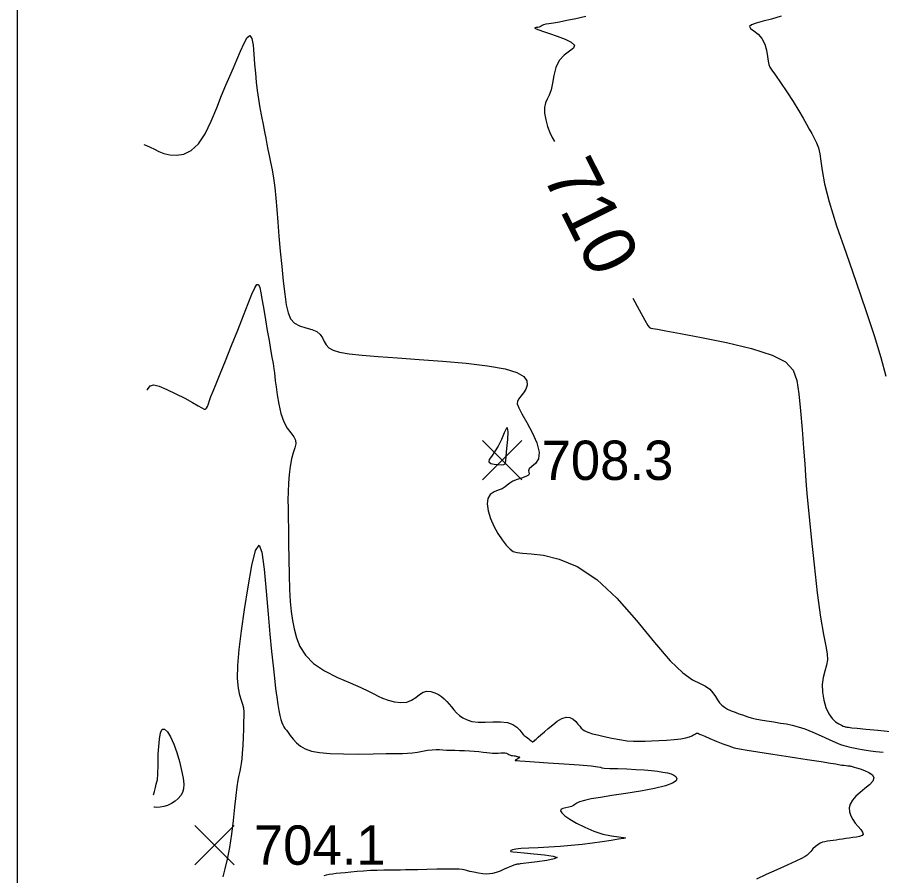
# Model space of a CAD drawing. Extents: x 2566142 to 2571431, y 418755 to 421584.
# Drawn here: x 2566164.4 to 2566493.5, y 419088.7 to 419415.7 of the extents above; entities that cross this region are included whole.
import ezdxf

# ---------------------------------------------------------------- set-up
doc = ezdxf.new("R2010")
doc.units = 0
for name, color, linetype in [('Contour_ADS_Label_Major', 7, 'Continuous'), ('Contour_ADS_Major', 7, 'Continuous'), ('Contour_ADS_Minor', 7, 'Continuous'), ('Contour_ADS_Spot_Elevation', 7, 'Continuous'), ('Contour_ADS_State_Plane_Border', 7, 'Continuous')]:
    doc.layers.add(name, color=color, linetype=linetype)

# ---------------------------------------------------------------- blocks, each defined once
blk = doc.blocks.new('S750')
at = {"layer": 'Contour_ADS_Spot_Elevation'}
for p, q in [((-0.5, 0.498), (0.5, -0.498)), ((-0.498, -0.5), (0.498, 0.5))]:
    blk.add_line(p, q, dxfattribs=at)

msp = doc.modelspace()

# ---------------------------------------------------------------- linework, layer by layer
at = {"layer": 'Contour_ADS_Major'}
for points in [[(2566380.87, 419416.02), (2566377.03, 419415.21), (2566373.64, 419414.5), (2566370.78, 419413.94), (2566368.53, 419413.55), (2566366.84, 419413.29), (2566365.61, 419413.09), (2566364.78, 419412.9), (2566364.25, 419412.67), (2566363.89, 419412.42), (2566363.56, 419412.19), (2566363.14, 419412.01), (2566362.55, 419411.91), (2566361.92, 419411.84), (2566361.48, 419411.76), (2566361.41, 419411.6), (2566361.9, 419411.33), (2566363, 419410.9), (2566364.72, 419410.31), (2566367.08, 419409.52), (2566369.99, 419408.54), (2566372.95, 419407.43), (2566375.34, 419406.26), (2566376.56, 419405.11), (2566376.2, 419404), (2566374.69, 419402.79), (2566372.67, 419401.27), (2566370.77, 419399.24), (2566369.48, 419396.6), (2566368.69, 419393.61), (2566368.16, 419390.65), (2566367.63, 419388.07), (2566366.92, 419386.13), (2566366.14, 419384.6), (2566365.47, 419383.14), (2566365.1, 419381.41), (2566365.16, 419379.19), (2566365.59, 419376.65), (2566366.27, 419374.09), (2566367.11, 419371.8), (2566368.02, 419369.94), (2566368.93, 419368.4)], [(2566398.76, 419308.78), (2566401.19, 419304.24), (2566403.3, 419300.36), (2566404.48, 419298.33), (2566405.13, 419297.52), (2566405.63, 419297.33), (2566406.41, 419297.19), (2566408.1, 419296.9), (2566411.37, 419296.32), (2566416.89, 419295.31), (2566424.96, 419293.8), (2566434.45, 419291.84), (2566443.88, 419289.56), (2566451.74, 419287.08), (2566456.92, 419284.43), (2566459.83, 419281.33), (2566461.24, 419277.4), (2566461.94, 419272.28), (2566462.55, 419265.81), (2566463.17, 419258.65), (2566463.74, 419251.64), (2566464.19, 419245.66), (2566464.51, 419241.21), (2566464.79, 419237.39), (2566465.15, 419232.95), (2566465.74, 419226.64), (2566466.63, 419217.67), (2566467.75, 419207.1), (2566468.99, 419196.45), (2566470.22, 419187.23), (2566471.32, 419180.6), (2566472.2, 419176.18), (2566472.75, 419173.23), (2566472.87, 419171), (2566472.51, 419168.87), (2566471.88, 419166.63), (2566471.24, 419164.22), (2566470.85, 419161.56), (2566470.91, 419158.63), (2566471.41, 419155.62), (2566472.24, 419152.79), (2566473.34, 419150.39), (2566474.6, 419148.59), (2566475.91, 419147.35), (2566477.14, 419146.54), (2566478.14, 419146.04), (2566478.84, 419145.74), (2566479.29, 419145.57), (2566479.59, 419145.49), (2566479.84, 419145.43), (2566480.18, 419145.36), (2566480.84, 419145.26), (2566482.09, 419145.11), (2566484.21, 419144.88), (2566487.44, 419144.57), (2566491.97, 419144.13), (2566497.99, 419143.49)]]:
    msp.add_lwpolyline(points, dxfattribs=at)
at = {"layer": 'Contour_ADS_Minor'}
for points in [[(2566455.17, 419416.17), (2566451.58, 419415.08), (2566448.34, 419414.2), (2566445.72, 419413.47), (2566443.93, 419412.82), (2566443.19, 419412.18), (2566443.6, 419411.48), (2566444.83, 419410.58), (2566446.42, 419409.37), (2566447.92, 419407.71), (2566448.98, 419405.55), (2566449.64, 419403.16), (2566450.02, 419400.85), (2566450.26, 419398.97), (2566450.51, 419397.71), (2566450.93, 419396.73), (2566451.71, 419395.55), (2566453.03, 419393.69), (2566454.99, 419390.85), (2566457.35, 419387.33), (2566459.78, 419383.61), (2566461.96, 419380.15), (2566463.65, 419377.32), (2566464.92, 419375.04), (2566465.94, 419373.13), (2566466.84, 419371.42), (2566467.77, 419369.73), (2566468.66, 419367.95), (2566469.44, 419365.97), (2566470.01, 419363.69), (2566470.38, 419360.95), (2566470.83, 419357.32), (2566471.75, 419352.3), (2566473.51, 419345.39), (2566476.34, 419336.35), (2566479.92, 419325.84), (2566483.79, 419314.77), (2566487.48, 419304.06), (2566490.61, 419294.47), (2566493.15, 419286.12), (2566495.13, 419278.99)], [(2566212.63, 419367.3), (2566213.61, 419366.95), (2566215.06, 419366.31), (2566216.62, 419365.52), (2566218.34, 419364.66), (2566220.28, 419363.89), (2566222.51, 419363.33), (2566225.06, 419363.15), (2566227.83, 419363.6), (2566230.66, 419364.96), (2566233.42, 419367.52), (2566235.96, 419371.39), (2566238.27, 419376.15), (2566240.35, 419381.2), (2566242.2, 419385.94), (2566243.83, 419389.93), (2566245.3, 419393.33), (2566246.68, 419396.44), (2566248.04, 419399.56), (2566249.43, 419402.86), (2566250.78, 419405.88), (2566252, 419408.05), (2566253, 419408.77), (2566253.71, 419407.65), (2566254.19, 419405.09), (2566254.52, 419401.65), (2566254.79, 419397.93), (2566255.08, 419394.39), (2566255.41, 419391.04), (2566255.8, 419387.8), (2566256.27, 419384.55), (2566256.82, 419381.25), (2566257.41, 419377.98), (2566258.01, 419374.87), (2566258.55, 419372.06), (2566259.01, 419369.63), (2566259.42, 419367.45), (2566259.83, 419365.32), (2566260.29, 419363.07), (2566260.83, 419360.52), (2566261.41, 419357.65), (2566261.99, 419354.44), (2566262.5, 419350.85), (2566262.91, 419346.89), (2566263.26, 419342.51), (2566263.62, 419337.69), (2566264.02, 419332.38), (2566264.52, 419326.64), (2566265.09, 419320.77), (2566265.69, 419315.16), (2566266.27, 419310.2), (2566266.82, 419306.18), (2566267.5, 419303.09), (2566268.46, 419300.8), (2566269.91, 419299.19), (2566271.92, 419298.14), (2566274.23, 419297.42), (2566276.52, 419296.79), (2566278.44, 419296.02), (2566279.74, 419294.92), (2566280.59, 419293.6), (2566281.24, 419292.21), (2566281.96, 419290.9), (2566283, 419289.81), (2566284.62, 419288.92), (2566287.11, 419288.19), (2566290.72, 419287.57), (2566295.66, 419287.01), (2566301.85, 419286.49), (2566309.14, 419285.95), (2566317.38, 419285.38), (2566326.33, 419284.72), (2566335.29, 419283.94), (2566343.49, 419282.99), (2566350.13, 419281.84), (2566354.64, 419280.44), (2566357.25, 419278.89), (2566358.39, 419277.25), (2566358.5, 419275.63), (2566357.99, 419274.09), (2566357.13, 419272.68), (2566356.16, 419271.43), (2566355.31, 419270.37), (2566354.81, 419269.46), (2566354.78, 419268.43), (2566355.32, 419266.95), (2566356.52, 419264.66), (2566358.38, 419261.39), (2566360.46, 419257.52), (2566362.22, 419253.59), (2566363.13, 419250.13), (2566362.83, 419247.56), (2566361.72, 419245.78), (2566360.35, 419244.57), (2566359.31, 419243.71), (2566359.01, 419243), (2566359.15, 419242.39), (2566359.31, 419241.83), (2566359.02, 419241.3), (2566357.99, 419240.77), (2566356.42, 419240.21)], [(2566214.03, 419273.72), (2566214.06, 419273.88), (2566214.96, 419275.36), (2566216.36, 419275.72), (2566218.48, 419275.17), (2566221.42, 419273.96), (2566224.82, 419272.34), (2566228.23, 419270.59), (2566231.18, 419268.98), (2566233.3, 419267.74), (2566234.7, 419266.92), (2566235.57, 419266.49), (2566236.12, 419266.46), (2566236.51, 419266.81), (2566236.84, 419267.5), (2566237.18, 419268.5), (2566237.6, 419269.75), (2566238.16, 419271.27), (2566238.97, 419273.29), (2566240.11, 419276.07), (2566241.68, 419279.9), (2566243.71, 419284.92), (2566246.03, 419290.68), (2566248.39, 419296.6), (2566250.55, 419302.11), (2566252.33, 419306.72), (2566253.74, 419310.27), (2566254.82, 419312.69), (2566255.64, 419313.92), (2566256.24, 419313.94), (2566256.72, 419312.84), (2566257.16, 419310.78), (2566257.65, 419307.9), (2566258.24, 419304.37), (2566258.91, 419300.45), (2566259.61, 419296.43), (2566260.27, 419292.61), (2566260.86, 419289.21), (2566261.37, 419286.29), (2566261.78, 419283.84), (2566262.08, 419281.87), (2566262.29, 419280.3), (2566262.46, 419278.85), (2566262.65, 419277.18), (2566262.93, 419274.93), (2566263.36, 419271.89), (2566263.97, 419268.36), (2566264.8, 419264.8), (2566265.87, 419261.63), (2566267.17, 419259.2), (2566268.51, 419257.38), (2566269.66, 419255.94), (2566270.36, 419254.64), (2566270.48, 419253.27), (2566270.12, 419251.69), (2566269.51, 419249.8), (2566268.85, 419247.48), (2566268.31, 419244.67), (2566267.92, 419241.51), (2566267.66, 419238.21), (2566267.52, 419234.96), (2566267.48, 419231.88), (2566267.52, 419228.71), (2566267.6, 419225.1), (2566267.68, 419220.7), (2566267.74, 419215.31), (2566267.8, 419209.34), (2566267.89, 419203.32), (2566268.04, 419197.81), (2566268.28, 419193.22), (2566268.64, 419189.38), (2566269.14, 419185.98), (2566269.8, 419182.73), (2566270.68, 419179.39), (2566272.03, 419176), (2566274.12, 419172.69), (2566277.21, 419169.58), (2566281.44, 419166.75), (2566286.28, 419164.27), (2566291.09, 419162.14), (2566295.2, 419160.41), (2566298.12, 419159.06), (2566300.16, 419158.02), (2566301.78, 419157.16), (2566303.46, 419156.38), (2566305.57, 419155.61), (2566307.97, 419154.98), (2566310.42, 419154.66), (2566312.67, 419154.82), (2566314.55, 419155.57), (2566316.13, 419156.66), (2566317.54, 419157.8), (2566318.93, 419158.66), (2566320.4, 419159.01), (2566321.9, 419158.9), (2566323.37, 419158.44), (2566324.73, 419157.77), (2566325.94, 419156.97), (2566327, 419156.08), (2566327.97, 419155.11), (2566328.87, 419154.07)], [(2566356.42, 419240.21), (2566354.67, 419239.62), (2566353.08, 419238.97), (2566351.9, 419238.26), (2566350.98, 419237.52), (2566350.1, 419236.81), (2566349, 419236.16), (2566347.53, 419235.58), (2566345.92, 419234.91), (2566344.48, 419233.94), (2566343.51, 419232.46), (2566343.26, 419230.33), (2566343.67, 419227.72), (2566344.58, 419224.83), (2566345.86, 419221.89), (2566347.38, 419219.11), (2566348.99, 419216.64), (2566350.57, 419214.59), (2566352, 419213.1), (2566353.24, 419212.24), (2566354.68, 419211.82), (2566356.78, 419211.61), (2566360.02, 419211.36), (2566364.74, 419210.78), (2566370.72, 419209.34), (2566377.6, 419206.47), (2566385.03, 419201.59), (2566392.66, 419194.42), (2566400.1, 419185.99), (2566407.01, 419177.61), (2566413, 419170.63), (2566417.81, 419166.02), (2566421.53, 419163.37), (2566424.35, 419161.92), (2566426.46, 419160.91), (2566428.04, 419159.73), (2566429.23, 419158.38), (2566430.17, 419156.99), (2566430.97, 419155.69), (2566431.77, 419154.59), (2566432.63, 419153.68), (2566433.62, 419152.91), (2566434.79, 419152.21), (2566436.18, 419151.57), (2566437.68, 419150.97), (2566439.16, 419150.43), (2566440.48, 419149.96), (2566441.58, 419149.57), (2566442.6, 419149.22), (2566443.78, 419148.89), (2566445.33, 419148.54), (2566447.39, 419148.14), (2566449.82, 419147.72), (2566452.4, 419147.29), (2566454.92, 419146.89), (2566457.21, 419146.52), (2566459.4, 419146.1), (2566461.7, 419145.49), (2566464.29, 419144.61), (2566467.29, 419143.38), (2566470.45, 419141.97), (2566473.45, 419140.59), (2566475.99, 419139.44), (2566477.81, 419138.69), (2566479.1, 419138.26), (2566480.08, 419138.02), (2566481.02, 419137.83), (2566482.12, 419137.59), (2566483.37, 419137.3), (2566484.72, 419137.01), (2566486.12, 419136.74), (2566487.56, 419136.52), (2566489.23, 419136.31), (2566491.32, 419136.07), (2566494.05, 419135.75)], [(2566242.77, 419088.28), (2566243.61, 419091.29), (2566244.5, 419095.03), (2566245.37, 419099.47), (2566246.11, 419104.51), (2566246.74, 419109.78), (2566247.28, 419114.82), (2566247.75, 419119.21), (2566248.18, 419122.61), (2566248.57, 419125.14), (2566248.93, 419127.06), (2566249.25, 419128.6), (2566249.54, 419130), (2566249.8, 419131.48), (2566250.02, 419133.23), (2566250.22, 419135.46), (2566250.38, 419138.28), (2566250.52, 419141.43), (2566250.63, 419144.57), (2566250.73, 419147.35), (2566250.81, 419149.5), (2566250.81, 419151.17), (2566250.67, 419152.57), (2566250.34, 419153.92), (2566249.78, 419155.46), (2566249.14, 419157.45), (2566248.59, 419160.16), (2566248.31, 419163.87), (2566248.43, 419168.77), (2566248.94, 419174.84), (2566249.79, 419181.97), (2566250.92, 419190.07), (2566252.26, 419198.79), (2566253.7, 419206.83), (2566255.14, 419212.64), (2566256.45, 419214.68), (2566257.55, 419211.93), (2566258.46, 419205.52), (2566259.23, 419197.12), (2566259.93, 419188.4), (2566260.59, 419180.7), (2566261.21, 419174.18), (2566261.79, 419168.67), (2566262.32, 419164.01), (2566262.79, 419160.06), (2566263.21, 419156.72), (2566263.61, 419153.94), (2566263.99, 419151.64), (2566264.37, 419149.76), (2566264.75, 419148.25), (2566265.14, 419147.06), (2566265.52, 419146.15), (2566265.9, 419145.45), (2566266.34, 419144.84), (2566266.86, 419144.17), (2566267.52, 419143.29), (2566268.37, 419142.13), (2566269.43, 419140.76), (2566270.71, 419139.36), (2566272.23, 419138.06), (2566274.06, 419137), (2566276.39, 419136.18), (2566279.47, 419135.6), (2566283.53, 419135.24)], [(2566328.87, 419154.07), (2566329.76, 419152.99), (2566330.67, 419151.88), (2566331.66, 419150.8), (2566332.78, 419149.77), (2566334.08, 419148.84), (2566335.64, 419148.06), (2566337.53, 419147.5), (2566339.83, 419147.22), (2566342.56, 419147.23), (2566345.52, 419147.36), (2566348.42, 419147.39), (2566351, 419147.09), (2566353.04, 419146.32), (2566354.58, 419145.25), (2566355.7, 419144.1), (2566356.49, 419143.12), (2566357.05, 419142.49), (2566357.45, 419142.12), (2566357.79, 419141.88), (2566358.15, 419141.63), (2566358.61, 419141.28), (2566359.11, 419140.86), (2566359.6, 419140.44), (2566360, 419140.1), (2566360.27, 419139.88), (2566360.44, 419139.77), (2566360.53, 419139.73), (2566360.6, 419139.74), (2566360.67, 419139.75), (2566360.75, 419139.78), (2566360.83, 419139.81), (2566360.91, 419139.84), (2566360.99, 419139.9), (2566361.15, 419140.03), (2566361.45, 419140.29), (2566361.96, 419140.75), (2566362.75, 419141.45), (2566363.8, 419142.38), (2566365.09, 419143.51), (2566366.59, 419144.82), (2566368.25, 419146.24), (2566369.99, 419147.58), (2566371.72, 419148.62), (2566373.34, 419149.14), (2566374.77, 419148.99), (2566376, 419148.34), (2566377.03, 419147.41), (2566377.88, 419146.44), (2566378.56, 419145.63), (2566379.13, 419144.98), (2566379.68, 419144.45), (2566380.27, 419144.01), (2566380.99, 419143.62), (2566381.97, 419143.23), (2566383.35, 419142.81), (2566385.27, 419142.32), (2566387.8, 419141.73), (2566390.72, 419141.12), (2566393.74, 419140.56), (2566396.57, 419140.15), (2566399.02, 419139.95), (2566401.23, 419139.92), (2566403.43, 419140), (2566405.85, 419140.13), (2566408.65, 419140.26), (2566411.62, 419140.41), (2566414.5, 419140.6), (2566417, 419140.87), (2566418.92, 419141.22), (2566420.3, 419141.63), (2566421.24, 419142.02), (2566421.86, 419142.34), (2566422.26, 419142.56), (2566422.5, 419142.68), (2566422.65, 419142.75), (2566422.77, 419142.81), (2566422.89, 419142.89), (2566423.04, 419142.96), (2566423.18, 419143.02), (2566423.33, 419143.05), (2566423.46, 419143.03), (2566423.57, 419142.98), (2566423.68, 419142.91), (2566423.77, 419142.84), (2566423.89, 419142.77), (2566424.2, 419142.64), (2566424.88, 419142.35), (2566426.14, 419141.82), (2566428.07, 419141), (2566430.45, 419140.01), (2566432.97, 419139), (2566435.31, 419138.13), (2566437.32, 419137.49), (2566439.43, 419136.99), (2566442.23, 419136.5), (2566446.33, 419135.87), (2566452.05, 419135.02), (2566458.65, 419134.02), (2566465.14, 419133.04), (2566470.51, 419132.21)], [(2566217.33, 419123.61), (2566217.58, 419124.52), (2566217.76, 419125.21), (2566217.87, 419125.9), (2566217.94, 419126.85), (2566217.97, 419128.24), (2566218, 419130.09), (2566218.04, 419132.36), (2566218.12, 419135.01), (2566218.27, 419137.94), (2566218.53, 419140.78), (2566218.96, 419143.1), (2566219.61, 419144.48), (2566220.5, 419144.6), (2566221.58, 419143.56), (2566222.77, 419141.57), (2566223.97, 419138.85), (2566225.12, 419135.63), (2566226.14, 419132.19), (2566226.97, 419128.85), (2566227.54, 419125.91), (2566227.8, 419123.6), (2566227.73, 419121.83), (2566227.36, 419120.43), (2566226.67, 419119.23), (2566225.69, 419118.1), (2566224.48, 419117.06), (2566223.1, 419116.17), (2566221.65, 419115.48), (2566220.18, 419115.04), (2566218.8, 419114.81), (2566217.6, 419114.75), (2566216.66, 419114.79), (2566216.4, 419114.84)], [(2566283.53, 419135.24), (2566288.66, 419135.09), (2566294.35, 419135.08), (2566299.95, 419135.15), (2566304.8, 419135.23), (2566308.41, 419135.26), (2566311.02, 419135.29), (2566313.02, 419135.35), (2566314.82, 419135.51), (2566316.73, 419135.8), (2566318.72, 419136.15), (2566320.65, 419136.48), (2566322.41, 419136.72), (2566323.9, 419136.79), (2566325.21, 419136.75), (2566326.46, 419136.65), (2566327.79, 419136.55), (2566329.3, 419136.5), (2566330.97, 419136.49), (2566332.77, 419136.47), (2566334.64, 419136.42), (2566336.55, 419136.32), (2566338.42, 419136.16), (2566340.19, 419135.99), (2566341.78, 419135.8), (2566343.14, 419135.63), (2566344.33, 419135.49), (2566345.4, 419135.4), (2566346.43, 419135.37), (2566347.47, 419135.42), (2566348.47, 419135.49), (2566349.38, 419135.54), (2566350.14, 419135.51), (2566350.71, 419135.38), (2566351.14, 419135.17), (2566351.53, 419134.93), (2566351.94, 419134.72), (2566352.44, 419134.57), (2566352.99, 419134.47), (2566353.53, 419134.39), (2566353.99, 419134.32), (2566354.33, 419134.24), (2566354.58, 419134.16), (2566354.79, 419134.07), (2566355.01, 419134.01), (2566355.26, 419133.97), (2566355.5, 419133.94), (2566355.64, 419133.87), (2566355.6, 419133.74), (2566355.35, 419133.54), (2566354.96, 419133.28), (2566354.53, 419133.03), (2566354.17, 419132.83), (2566353.97, 419132.7), (2566353.94, 419132.64), (2566354.06, 419132.62), (2566354.31, 419132.61), (2566354.75, 419132.57), (2566355.77, 419132.5), (2566357.81, 419132.35), (2566361.33, 419132.11), (2566366.53, 419131.75), (2566372.57, 419131.34), (2566378.39, 419130.91), (2566382.91, 419130.53), (2566385.38, 419130.23), (2566386.41, 419130.01), (2566386.94, 419129.85), (2566387.89, 419129.73), (2566389.98, 419129.62), (2566392.99, 419129.51), (2566396.47, 419129.38), (2566399.95, 419129.22), (2566403.08, 419129.01), (2566405.81, 419128.77), (2566408.16, 419128.49), (2566410.19, 419128.2), (2566411.91, 419127.88), (2566413.32, 419127.52), (2566414.41, 419127.07), (2566415.17, 419126.49), (2566415.54, 419125.76), (2566415.23, 419124.9), (2566413.9, 419123.95), (2566411.2, 419122.96), (2566406.96, 419121.95), (2566401.7, 419120.98), (2566396.08, 419120.06), (2566390.79, 419119.25), (2566386.39, 419118.56), (2566382.91, 419117.96), (2566380.31, 419117.42), (2566378.5, 419116.91), (2566377.38, 419116.39), (2566376.7, 419115.89), (2566376.16, 419115.45), (2566375.47, 419115.09), (2566374.45, 419114.84), (2566373.25, 419114.63), (2566372.14, 419114.37), (2566371.38, 419113.99)], [(2566470.51, 419132.21), (2566474.03, 419131.64), (2566476.01, 419131.28), (2566477.03, 419131.08), (2566477.67, 419130.96), (2566478.38, 419130.86), (2566479.19, 419130.77), (2566479.96, 419130.69), (2566480.6, 419130.63), (2566481.03, 419130.59), (2566481.32, 419130.55), (2566481.56, 419130.5), (2566481.85, 419130.43), (2566482.3, 419130.31), (2566482.97, 419130.12), (2566483.93, 419129.83), (2566485.25, 419129.4), (2566486.93, 419128.81), (2566488.64, 419128.05), (2566489.98, 419127.11), (2566490.55, 419126.01), (2566490.08, 419124.75), (2566488.8, 419123.37), (2566487.06, 419121.91), (2566485.25, 419120.43), (2566483.66, 419118.96), (2566482.41, 419117.5), (2566481.55, 419116.03), (2566481.14, 419114.56), (2566481.21, 419113.07), (2566481.69, 419111.58), (2566482.47, 419110.13), (2566483.46, 419108.74), (2566484.54, 419107.45), (2566485.53, 419106.3), (2566486.23, 419105.32), (2566486.44, 419104.54), (2566486.02, 419104), (2566485.1, 419103.64), (2566483.87, 419103.39), (2566482.5, 419103.21), (2566481.16, 419103.02), (2566479.86, 419102.84), (2566478.6, 419102.65), (2566477.36, 419102.47), (2566476.15, 419102.3), (2566474.98, 419102.14), (2566473.87, 419101.99), (2566472.83, 419101.83), (2566471.87, 419101.66), (2566470.96, 419101.43), (2566470.08, 419101.08), (2566469.18, 419100.54), (2566468.25, 419099.78), (2566467.32, 419098.89), (2566466.46, 419097.98), (2566465.73, 419097.19), (2566465.12, 419096.56), (2566464.34, 419095.98), (2566463.03, 419095.27), (2566460.84, 419094.23), (2566457.57, 419092.77), (2566453.61, 419091.01), (2566449.51, 419089.15), (2566445.82, 419087.42)], [(2566216.33, 419119.48), (2566216.62, 419120.74), (2566216.99, 419122.29), (2566217.33, 419123.61)], [(2566371.38, 419113.99), (2566371.21, 419113.41), (2566371.69, 419112.61), (2566372.85, 419111.58), (2566374.75, 419110.29), (2566377.35, 419108.78), (2566380.48, 419107.19), (2566383.89, 419105.73), (2566387.36, 419104.57), (2566390.63, 419103.85), (2566393.38, 419103.47), (2566395.27, 419103.29), (2566395.98, 419103.14), (2566395.27, 419102.91), (2566393.35, 419102.58), (2566390.53, 419102.16), (2566387.11, 419101.68), (2566383.38, 419101.16), (2566379.42, 419100.64), (2566375.3, 419100.17), (2566371.07, 419099.79), (2566366.82, 419099.53), (2566362.77, 419099.37), (2566359.17, 419099.23), (2566356.26, 419099.08), (2566354.23, 419098.87), (2566352.98, 419098.62), (2566352.34, 419098.37), (2566352.17, 419098.15), (2566352.36, 419097.98), (2566353.11, 419097.84), (2566354.68, 419097.67), (2566357.33, 419097.44), (2566361.1, 419097.1), (2566365.16, 419096.68), (2566368.45, 419096.19), (2566369.91, 419095.65), (2566368.86, 419095.09), (2566365.99, 419094.54), (2566362.39, 419094.05), (2566359.11, 419093.66), (2566357.01, 419093.4), (2566355.92, 419093.25), (2566355.5, 419093.17), (2566355.35, 419093.13), (2566355.17, 419093.1), (2566354.94, 419093.07), (2566354.68, 419093.05), (2566354.43, 419093.02), (2566354.21, 419092.99), (2566353.9, 419092.91), (2566353.4, 419092.71), (2566352.57, 419092.36), (2566351.33, 419091.82), (2566349.82, 419091.16), (2566348.21, 419090.5), (2566346.69, 419089.94), (2566345.38, 419089.57), (2566344.2, 419089.38), (2566342.99, 419089.36), (2566341.62, 419089.48), (2566340, 419089.72), (2566338.28, 419090.04), (2566336.67, 419090.38), (2566335.38, 419090.69), (2566334.51, 419090.93), (2566333.73, 419091.09), (2566332.61, 419091.19), (2566330.72, 419091.23), (2566327.77, 419091.21), (2566324.13, 419091.16), (2566320.34, 419091.08), (2566316.91, 419091.01), (2566314.24, 419090.94), (2566312.16, 419090.89), (2566310.35, 419090.85), (2566308.5, 419090.83), (2566306.37, 419090.82), (2566303.99, 419090.8), (2566301.45, 419090.76), (2566298.85, 419090.66), (2566296.26, 419090.5), (2566293.77, 419090.29), (2566291.42, 419090.07), (2566289.29, 419089.86), (2566287.42, 419089.67), (2566285.8, 419089.51), (2566284.38, 419089.34), (2566283.13, 419089.13), (2566282.03, 419088.89), (2566281.09, 419088.61)]]:
    msp.add_lwpolyline(points, dxfattribs=at)
msp.add_lwpolyline([(2566351.11, 419259.4), (2566350.63, 419259.15), (2566349.83, 419257.43), (2566348.77, 419254.94), (2566347.51, 419252.32), (2566346.14, 419250.15), (2566344.91, 419248.46), (2566344.09, 419247.22), (2566343.95, 419246.35), (2566344.66, 419245.8), (2566345.94, 419245.48), (2566347.44, 419245.34), (2566348.76, 419245.28), (2566349.62, 419245.31), (2566350.1, 419245.66), (2566350.37, 419246.64), (2566350.58, 419248.55), (2566350.85, 419251.51), (2566351.12, 419254.86), (2566351.24, 419257.78), (2566351.11, 419259.4)], close=True, dxfattribs=at)
at = {"layer": 'Contour_ADS_State_Plane_Border'}
msp.add_lwpolyline([(2566164.43, 418777.5), (2571407.81, 418777.5), (2571407.81, 421561.67), (2566164.43, 421561.67), (2566164.43, 418777.5)], close=True, dxfattribs=at)

# ---------------------------------------------------------------- block references
at = {"layer": 'Contour_ADS_Spot_Elevation', "xscale": 15, "yscale": 15}
for p in [(2566349, 419246.98), (2566239.47, 419100.37)]:
    msp.add_blockref('S750', p, dxfattribs=at)

# ---------------------------------------------------------------- texts
at = {"layer": 'Contour_ADS_Label_Major'}
msp.add_text('710', height=20, rotation=296.581, dxfattribs=at).set_placement((2566364.14, 419355.62))
at = {"layer": 'Contour_ADS_Spot_Elevation'}
for s, p in [('708.3', (2566364, 419239.48)), ('704.1', (2566254.47, 419092.87))]:
    msp.add_text(s, height=15, dxfattribs=at).set_placement(p)

doc.saveas('drawing.dxf')
